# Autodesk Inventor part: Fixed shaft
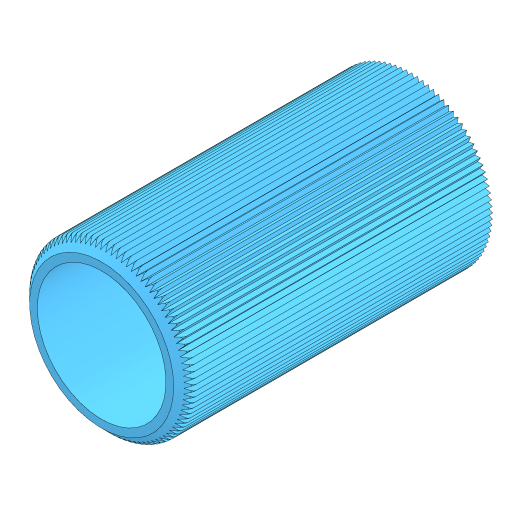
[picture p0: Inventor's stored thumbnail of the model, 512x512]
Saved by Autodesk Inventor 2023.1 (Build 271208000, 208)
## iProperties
Created: 2020-02
Part Number: Fixed shaft
Material: Generic
Document SubType Name: Modeling
Designer: ftrauzettel
Density: 1 g/cm^3
Appearance: Default
Sending System: SolidWorks 2016
Last Author: Pam
Last Saved: 2020-02-23
Author: ftrauzettel
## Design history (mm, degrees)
feature "Tap Drill Slot for M2 Tap1"
body "Solid1"
